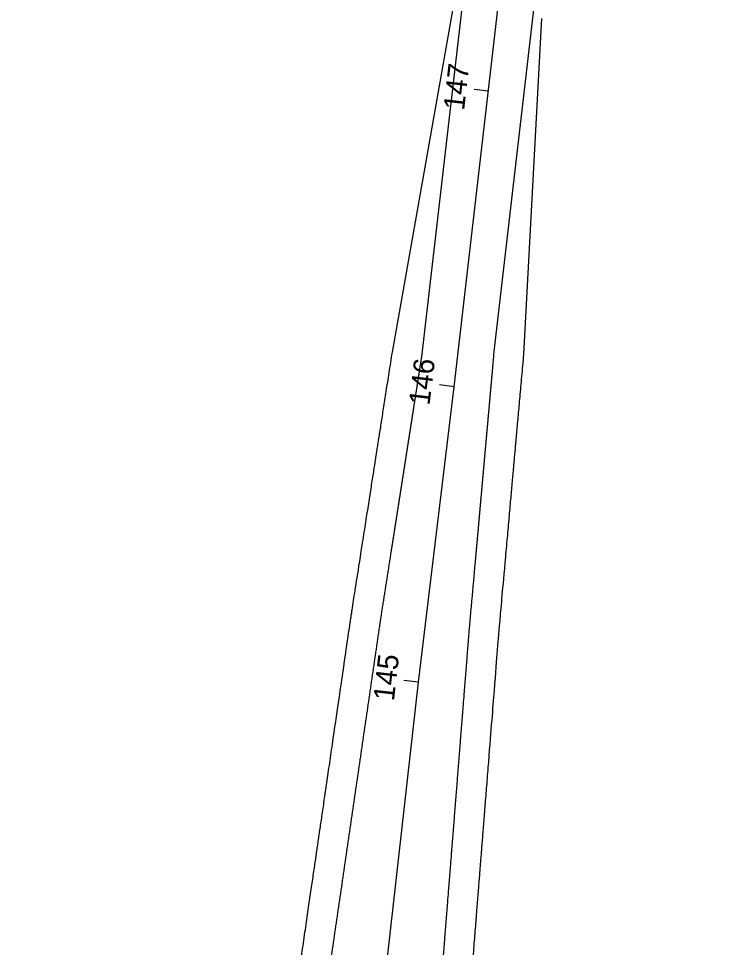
# Model space of a CAD drawing. Extents: x 2318076 to 2324211, y 613525 to 629939.
# Drawn here: x 2320544.3 to 2320778.2, y 628975.4 to 629287.5 of the extents above; entities that cross this region are included whole.
import ezdxf

# ---------------------------------------------------------------- set-up
doc = ezdxf.new("R2010")
doc.units = 0
for name, color, linetype in [('GE_P_CL_50', 7, 'Continuous'), ('PV_P_EOP', 7, 'Continuous'), ('PV_P_Shoulder', 7, 'Continuous')]:
    doc.layers.add(name, color=color, linetype=linetype)

msp = doc.modelspace()

# ---------------------------------------------------------------- linework, layer by layer
at = {"layer": 'GE_P_CL_50'}
for p, q in [((2320702.26, 629263.11), (2320697.41, 629263.67)), ((2320690.76, 629163.78), (2320685.8, 629164.39)), ((2320678.77, 629064.5), (2320673.8, 629065.06))]:
    msp.add_line(p, q, dxfattribs=at)
msp.add_lwpolyline([(2320485.22, 627375.57), (2320502.11, 627520.92), (2320519.22, 627676.47), (2320531.82, 627783.89), (2320546.8, 627927.12), (2320554.45, 627991.34), (2320572.51, 628138.41), (2320649.52, 628804.84), (2320678.77, 629064.5), (2320690.76, 629163.78), (2320713.75, 629362.45), (2320725.26, 629461.78), (2320736.97, 629561.09), (2320748.4, 629660.43), (2320759.09, 629759.86), (2320769.62, 629859.3), (2320777.51, 629931.12), (2320778.25, 629937.84)], dxfattribs=at)
at = {"layer": 'PV_P_EOP'}
for points in [[(2320679.85, 629173.88), (2320701.83, 629363.83), (2320708.13, 629418.9), (2320708.13, 629418.9)], [(2320704.21, 629175.59), (2320725.67, 629361.07), (2320731.95, 629415.91), (2320731.95, 629415.91)]]:
    msp.add_lwpolyline(points, dxfattribs=at)
for points in [[(2320669.71, 629109.04), (2320669.76, 629109.34), (2320669.81, 629109.64), (2320669.85, 629109.94), (2320669.9, 629110.24), (2320669.95, 629110.54), (2320670, 629110.84), (2320670.04, 629111.14), (2320670.09, 629111.44), (2320670.14, 629111.74), (2320670.18, 629112.04), (2320670.23, 629112.34), (2320670.28, 629112.64), (2320670.32, 629112.94), (2320670.37, 629113.24), (2320670.42, 629113.54), (2320670.47, 629113.84), (2320670.51, 629114.14), (2320670.56, 629114.44), (2320670.61, 629114.74), (2320670.65, 629115.04), (2320670.7, 629115.35), (2320670.75, 629115.65), (2320670.79, 629115.95), (2320670.84, 629116.25), (2320670.89, 629116.55), (2320670.93, 629116.85), (2320670.98, 629117.15), (2320671.03, 629117.45), (2320671.08, 629117.75), (2320671.12, 629118.05), (2320671.17, 629118.35), (2320671.22, 629118.65), (2320671.26, 629118.95), (2320671.31, 629119.25), (2320671.36, 629119.55), (2320671.4, 629119.85), (2320671.45, 629120.15), (2320671.5, 629120.45), (2320671.55, 629120.75), (2320671.59, 629121.05), (2320671.64, 629121.35), (2320671.69, 629121.65), (2320671.73, 629121.95), (2320671.78, 629122.25), (2320671.83, 629122.55), (2320671.87, 629122.85), (2320671.92, 629123.15), (2320671.97, 629123.45), (2320672.01, 629123.75), (2320672.06, 629124.05), (2320672.11, 629124.35), (2320672.16, 629124.66), (2320672.2, 629124.96), (2320672.25, 629125.26), (2320672.3, 629125.56), (2320672.34, 629125.86), (2320672.39, 629126.16), (2320672.44, 629126.46), (2320672.48, 629126.76), (2320672.53, 629127.06), (2320672.58, 629127.36), (2320672.63, 629127.66), (2320672.67, 629127.96), (2320672.72, 629128.26), (2320672.77, 629128.56), (2320672.81, 629128.86), (2320672.86, 629129.16), (2320672.91, 629129.46), (2320672.95, 629129.76), (2320673, 629130.06), (2320673.05, 629130.36), (2320673.09, 629130.66), (2320673.14, 629130.96), (2320673.19, 629131.26), (2320673.24, 629131.56), (2320673.28, 629131.86), (2320673.33, 629132.16), (2320673.38, 629132.46), (2320673.42, 629132.76), (2320673.47, 629133.06), (2320673.52, 629133.36), (2320673.56, 629133.66), (2320673.61, 629133.97), (2320673.66, 629134.27), (2320673.71, 629134.57), (2320673.75, 629134.87), (2320673.8, 629135.17), (2320673.85, 629135.47), (2320673.89, 629135.77), (2320673.94, 629136.07), (2320673.99, 629136.37), (2320674.03, 629136.67), (2320674.08, 629136.97), (2320674.13, 629137.27), (2320674.17, 629137.57), (2320674.22, 629137.87), (2320674.27, 629138.17), (2320674.32, 629138.47), (2320674.36, 629138.77), (2320674.41, 629139.07), (2320674.46, 629139.37), (2320674.5, 629139.67), (2320674.55, 629139.97), (2320674.6, 629140.27), (2320674.64, 629140.57), (2320674.69, 629140.87), (2320674.74, 629141.17), (2320674.79, 629141.47), (2320674.83, 629141.77), (2320674.88, 629142.07), (2320674.93, 629142.37), (2320674.97, 629142.67), (2320675.02, 629142.97), (2320675.07, 629143.27), (2320675.11, 629143.58), (2320675.16, 629143.88), (2320675.21, 629144.18), (2320675.25, 629144.48), (2320675.3, 629144.78), (2320675.35, 629145.08), (2320675.4, 629145.38), (2320675.44, 629145.68), (2320675.49, 629145.98), (2320675.54, 629146.28), (2320675.58, 629146.58), (2320675.63, 629146.88), (2320675.68, 629147.18), (2320675.72, 629147.48), (2320675.77, 629147.78), (2320675.82, 629148.08), (2320675.87, 629148.38), (2320675.91, 629148.68), (2320675.96, 629148.98), (2320676.01, 629149.28), (2320676.05, 629149.58), (2320676.1, 629149.88), (2320676.15, 629150.18), (2320676.19, 629150.48), (2320676.24, 629150.78), (2320676.29, 629151.08), (2320676.33, 629151.38), (2320676.38, 629151.68), (2320676.43, 629151.98), (2320676.48, 629152.28), (2320676.52, 629152.58), (2320676.57, 629152.89), (2320676.62, 629153.19), (2320676.66, 629153.49), (2320676.71, 629153.79), (2320676.76, 629154.09), (2320676.8, 629154.39), (2320676.85, 629154.69), (2320676.9, 629154.99), (2320676.95, 629155.29), (2320676.99, 629155.59), (2320677.04, 629155.89), (2320677.09, 629156.19), (2320677.13, 629156.49), (2320677.18, 629156.79), (2320677.23, 629157.09), (2320677.27, 629157.39), (2320677.32, 629157.69), (2320677.37, 629157.99), (2320677.41, 629158.29), (2320677.46, 629158.59), (2320677.51, 629158.89), (2320677.56, 629159.19), (2320677.6, 629159.49), (2320677.65, 629159.79), (2320677.7, 629160.09), (2320677.74, 629160.39), (2320677.79, 629160.69), (2320677.84, 629160.99), (2320677.88, 629161.29), (2320677.93, 629161.59), (2320677.98, 629161.89), (2320678.03, 629162.2), (2320678.07, 629162.5), (2320678.12, 629162.8), (2320678.17, 629163.1), (2320678.21, 629163.4), (2320678.26, 629163.7), (2320678.31, 629164), (2320678.35, 629164.3), (2320678.4, 629164.6), (2320678.45, 629164.9), (2320678.49, 629165.2), (2320678.54, 629165.5), (2320678.59, 629165.8), (2320678.64, 629166.1), (2320678.68, 629166.4), (2320678.73, 629166.7), (2320678.78, 629167), (2320678.82, 629167.3), (2320678.87, 629167.6), (2320678.92, 629167.9), (2320678.96, 629168.2), (2320679.01, 629168.5), (2320679.06, 629168.8), (2320679.11, 629169.1), (2320679.15, 629169.4), (2320679.2, 629169.7), (2320679.25, 629170), (2320679.29, 629170.3), (2320679.34, 629170.6), (2320679.39, 629170.9), (2320679.43, 629171.2), (2320679.48, 629171.51), (2320679.53, 629171.81), (2320679.57, 629172.11), (2320679.62, 629172.41), (2320679.67, 629172.71), (2320679.72, 629173.01), (2320679.76, 629173.3), (2320679.81, 629173.59), (2320679.85, 629173.88)], [(2320697.95, 629105.57), (2320697.97, 629105.88), (2320698, 629106.18), (2320698.03, 629106.48), (2320698.05, 629106.78), (2320698.08, 629107.09), (2320698.11, 629107.39), (2320698.14, 629107.69), (2320698.16, 629107.99), (2320698.19, 629108.3), (2320698.22, 629108.6), (2320698.24, 629108.9), (2320698.27, 629109.21), (2320698.3, 629109.51), (2320698.33, 629109.81), (2320698.35, 629110.11), (2320698.38, 629110.42), (2320698.41, 629110.72), (2320698.43, 629111.02), (2320698.46, 629111.32), (2320698.49, 629111.63), (2320698.52, 629111.93), (2320698.54, 629112.23), (2320698.57, 629112.54), (2320698.6, 629112.84), (2320698.62, 629113.14), (2320698.65, 629113.44), (2320698.68, 629113.75), (2320698.7, 629114.05), (2320698.73, 629114.35), (2320698.76, 629114.66), (2320698.79, 629114.96), (2320698.81, 629115.26), (2320698.84, 629115.56), (2320698.87, 629115.87), (2320698.89, 629116.17), (2320698.92, 629116.47), (2320698.95, 629116.77), (2320698.98, 629117.08), (2320699, 629117.38), (2320699.03, 629117.68), (2320699.06, 629117.99), (2320699.08, 629118.29), (2320699.11, 629118.59), (2320699.14, 629118.89), (2320699.17, 629119.2), (2320699.19, 629119.5), (2320699.22, 629119.8), (2320699.25, 629120.1), (2320699.27, 629120.41), (2320699.3, 629120.71), (2320699.33, 629121.01), (2320699.35, 629121.32), (2320699.38, 629121.62), (2320699.41, 629121.92), (2320699.44, 629122.22), (2320699.46, 629122.53), (2320699.49, 629122.83), (2320699.52, 629123.13), (2320699.54, 629123.44), (2320699.57, 629123.74), (2320699.6, 629124.04), (2320699.63, 629124.34), (2320699.65, 629124.65), (2320699.68, 629124.95), (2320699.71, 629125.25), (2320699.73, 629125.55), (2320699.76, 629125.86), (2320699.79, 629126.16), (2320699.82, 629126.46), (2320699.84, 629126.77), (2320699.87, 629127.07), (2320699.9, 629127.37), (2320699.92, 629127.67), (2320699.95, 629127.98), (2320699.98, 629128.28), (2320700.01, 629128.58), (2320700.03, 629128.88), (2320700.06, 629129.19), (2320700.09, 629129.49), (2320700.11, 629129.79), (2320700.14, 629130.1), (2320700.17, 629130.4), (2320700.19, 629130.7), (2320700.22, 629131), (2320700.25, 629131.31), (2320700.28, 629131.61), (2320700.3, 629131.91), (2320700.33, 629132.22), (2320700.36, 629132.52), (2320700.38, 629132.82), (2320700.41, 629133.12), (2320700.44, 629133.43), (2320700.47, 629133.73), (2320700.49, 629134.03), (2320700.52, 629134.33), (2320700.55, 629134.64), (2320700.57, 629134.94), (2320700.6, 629135.24), (2320700.63, 629135.55), (2320700.66, 629135.85), (2320700.68, 629136.15), (2320700.71, 629136.45), (2320700.74, 629136.76), (2320700.76, 629137.06), (2320700.79, 629137.36), (2320700.82, 629137.66), (2320700.84, 629137.97), (2320700.87, 629138.27), (2320700.9, 629138.57), (2320700.93, 629138.88), (2320700.95, 629139.18), (2320700.98, 629139.48), (2320701.01, 629139.78), (2320701.03, 629140.09), (2320701.06, 629140.39), (2320701.09, 629140.69), (2320701.12, 629141), (2320701.14, 629141.3), (2320701.17, 629141.6), (2320701.2, 629141.9), (2320701.22, 629142.21), (2320701.25, 629142.51), (2320701.28, 629142.81), (2320701.31, 629143.11), (2320701.33, 629143.42), (2320701.36, 629143.72), (2320701.39, 629144.02), (2320701.41, 629144.33), (2320701.44, 629144.63), (2320701.47, 629144.93), (2320701.49, 629145.23), (2320701.52, 629145.54), (2320701.55, 629145.84), (2320701.58, 629146.14), (2320701.6, 629146.44), (2320701.63, 629146.75), (2320701.66, 629147.05), (2320701.68, 629147.35), (2320701.71, 629147.66), (2320701.74, 629147.96), (2320701.77, 629148.26), (2320701.79, 629148.56), (2320701.82, 629148.87), (2320701.85, 629149.17), (2320701.87, 629149.47), (2320701.9, 629149.78), (2320701.93, 629150.08), (2320701.96, 629150.38), (2320701.98, 629150.68), (2320702.01, 629150.99), (2320702.04, 629151.29), (2320702.06, 629151.59), (2320702.09, 629151.89), (2320702.12, 629152.2), (2320702.14, 629152.5), (2320702.17, 629152.8), (2320702.2, 629153.11), (2320702.23, 629153.41), (2320702.25, 629153.71), (2320702.28, 629154.01), (2320702.31, 629154.32), (2320702.33, 629154.62), (2320702.36, 629154.92), (2320702.39, 629155.22), (2320702.42, 629155.53), (2320702.44, 629155.83), (2320702.47, 629156.13), (2320702.5, 629156.44), (2320702.52, 629156.74), (2320702.55, 629157.04), (2320702.58, 629157.34), (2320702.61, 629157.65), (2320702.63, 629157.95), (2320702.66, 629158.25), (2320702.69, 629158.56), (2320702.71, 629158.86), (2320702.74, 629159.16), (2320702.77, 629159.46), (2320702.79, 629159.77), (2320702.82, 629160.07), (2320702.85, 629160.37), (2320702.88, 629160.67), (2320702.9, 629160.98), (2320702.93, 629161.28), (2320702.96, 629161.58), (2320702.98, 629161.89), (2320703.01, 629162.19), (2320703.04, 629162.49), (2320703.07, 629162.79), (2320703.09, 629163.1), (2320703.12, 629163.4), (2320703.15, 629163.7), (2320703.17, 629164), (2320703.2, 629164.31), (2320703.23, 629164.61), (2320703.26, 629164.91), (2320703.28, 629165.22), (2320703.31, 629165.52), (2320703.34, 629165.82), (2320703.36, 629166.12), (2320703.39, 629166.43), (2320703.42, 629166.73), (2320703.44, 629167.03), (2320703.47, 629167.34), (2320703.5, 629167.64), (2320703.53, 629167.94), (2320703.55, 629168.24), (2320703.58, 629168.55), (2320703.61, 629168.85), (2320703.63, 629169.15), (2320703.66, 629169.45), (2320703.69, 629169.76), (2320703.72, 629170.06), (2320703.74, 629170.36), (2320703.77, 629170.67), (2320703.8, 629170.97), (2320703.93, 629172.51), (2320704.07, 629174.05), (2320704.21, 629175.59)]]:
    msp.add_open_spline(points, degree=3, dxfattribs=at)
for points in [[(2320659.7, 629042.15), (2320659.83, 629043.06), (2320659.97, 629043.96), (2320660.1, 629044.86), (2320660.23, 629045.76), (2320660.36, 629046.67), (2320660.49, 629047.57), (2320660.63, 629048.47), (2320660.76, 629049.37), (2320660.89, 629050.27), (2320661.02, 629051.18), (2320661.15, 629052.08), (2320661.29, 629052.98), (2320661.42, 629053.88), (2320661.55, 629054.79), (2320661.68, 629055.69), (2320661.81, 629056.59), (2320661.94, 629057.49), (2320662.08, 629058.4), (2320662.21, 629059.3), (2320662.34, 629060.2), (2320662.47, 629061.1), (2320662.6, 629062), (2320662.74, 629062.91), (2320662.87, 629063.81), (2320663, 629064.71), (2320663.13, 629065.61), (2320663.26, 629066.52), (2320663.4, 629067.42), (2320663.53, 629068.32), (2320663.66, 629069.22), (2320663.79, 629070.13), (2320663.92, 629071.03), (2320664.05, 629071.93), (2320664.19, 629072.83), (2320664.32, 629073.73), (2320664.45, 629074.64), (2320664.58, 629075.54), (2320664.71, 629076.44), (2320664.85, 629077.34), (2320664.98, 629078.25), (2320665.11, 629079.15), (2320665.24, 629080.05), (2320665.37, 629080.95), (2320665.5, 629081.86), (2320665.64, 629082.76), (2320665.77, 629083.66), (2320665.9, 629084.56), (2320666.05, 629085.61), (2320666.19, 629086.51), (2320666.33, 629087.42), (2320666.47, 629088.32), (2320666.62, 629089.22), (2320666.76, 629090.12), (2320666.9, 629091.02), (2320667.04, 629091.92), (2320667.18, 629092.82), (2320667.32, 629093.72), (2320667.46, 629094.62), (2320667.6, 629095.52), (2320667.74, 629096.43), (2320667.88, 629097.33), (2320668.02, 629098.23), (2320668.16, 629099.13), (2320668.31, 629100.03), (2320668.45, 629100.93), (2320668.59, 629101.83), (2320668.73, 629102.73), (2320668.87, 629103.63), (2320669.01, 629104.53), (2320669.15, 629105.43), (2320669.29, 629106.34), (2320669.43, 629107.24), (2320669.57, 629108.14), (2320669.71, 629109.04)], [(2320692.39, 629038.47), (2320692.46, 629039.38), (2320692.53, 629040.29), (2320692.6, 629041.2), (2320692.67, 629042.11), (2320692.75, 629043.02), (2320692.82, 629043.93), (2320692.89, 629044.84), (2320692.96, 629045.74), (2320693.03, 629046.65), (2320693.11, 629047.56), (2320693.18, 629048.47), (2320693.25, 629049.38), (2320693.32, 629050.29), (2320693.4, 629051.2), (2320693.47, 629052.11), (2320693.54, 629053.02), (2320693.61, 629053.93), (2320693.68, 629054.83), (2320693.76, 629055.74), (2320693.83, 629056.65), (2320693.9, 629057.56), (2320693.97, 629058.47), (2320694.05, 629059.38), (2320694.12, 629060.29), (2320694.19, 629061.2), (2320694.26, 629062.11), (2320694.33, 629063.02), (2320694.41, 629063.93), (2320694.48, 629064.83), (2320694.55, 629065.74), (2320694.62, 629066.65), (2320694.69, 629067.56), (2320694.77, 629068.47), (2320694.84, 629069.38), (2320694.91, 629070.29), (2320694.98, 629071.2), (2320695.06, 629072.11), (2320695.13, 629073.02), (2320695.2, 629073.92), (2320695.27, 629074.83), (2320695.34, 629075.74), (2320695.42, 629076.65), (2320695.49, 629077.56), (2320695.56, 629078.47), (2320695.63, 629079.38), (2320695.71, 629080.29), (2320695.78, 629081.2), (2320695.83, 629081.96), (2320695.92, 629082.87), (2320696, 629083.77), (2320696.08, 629084.68), (2320696.16, 629085.59), (2320696.24, 629086.5), (2320696.32, 629087.41), (2320696.4, 629088.32), (2320696.48, 629089.22), (2320696.57, 629090.13), (2320696.65, 629091.04), (2320696.73, 629091.95), (2320696.81, 629092.86), (2320696.89, 629093.76), (2320696.97, 629094.67), (2320697.05, 629095.58), (2320697.13, 629096.49), (2320697.22, 629097.4), (2320697.3, 629098.31), (2320697.38, 629099.21), (2320697.46, 629100.12), (2320697.54, 629101.03), (2320697.62, 629101.94), (2320697.7, 629102.85), (2320697.78, 629103.76), (2320697.87, 629104.66), (2320697.95, 629105.57)], [(2320649.95, 628975.38), (2320650.08, 628976.28), (2320650.21, 628977.19), (2320650.34, 628978.09), (2320650.47, 628978.99), (2320650.6, 628979.89), (2320650.74, 628980.8), (2320650.87, 628981.7), (2320651, 628982.6), (2320651.13, 628983.5), (2320651.26, 628984.4), (2320651.4, 628985.31), (2320651.53, 628986.21), (2320651.66, 628987.11), (2320651.79, 628988.01), (2320651.92, 628988.92), (2320652.06, 628989.82), (2320652.19, 628990.72), (2320652.32, 628991.62), (2320652.45, 628992.53), (2320652.58, 628993.43), (2320652.71, 628994.33), (2320652.85, 628995.23), (2320652.98, 628996.13), (2320653.11, 628997.04), (2320653.24, 628997.94), (2320653.37, 628998.84), (2320653.51, 628999.74), (2320653.64, 629000.65), (2320653.77, 629001.55), (2320653.9, 629002.45), (2320654.03, 629003.35), (2320654.16, 629004.26), (2320654.3, 629005.16), (2320654.43, 629006.06), (2320654.56, 629006.96), (2320654.69, 629007.87), (2320654.82, 629008.77), (2320654.96, 629009.67), (2320655.09, 629010.57), (2320655.22, 629011.47), (2320655.35, 629012.38), (2320655.48, 629013.28), (2320655.62, 629014.18), (2320655.75, 629015.08), (2320655.88, 629015.99), (2320656.01, 629016.89), (2320656.14, 629017.79), (2320656.27, 629018.69), (2320656.41, 629019.6), (2320656.54, 629020.5), (2320656.67, 629021.4), (2320656.8, 629022.3), (2320656.93, 629023.2), (2320657.07, 629024.11), (2320657.2, 629025.01), (2320657.33, 629025.91), (2320657.46, 629026.81), (2320657.59, 629027.72), (2320657.73, 629028.62), (2320657.86, 629029.52), (2320657.99, 629030.42), (2320658.12, 629031.33), (2320658.25, 629032.23), (2320658.38, 629033.13), (2320658.52, 629034.03), (2320658.65, 629034.93), (2320658.78, 629035.84), (2320658.91, 629036.74), (2320659.04, 629037.64), (2320659.18, 629038.54), (2320659.31, 629039.45), (2320659.44, 629040.35), (2320659.57, 629041.25), (2320659.7, 629042.15)], [(2320687.04, 628971.2), (2320687.12, 628972.11), (2320687.19, 628973.02), (2320687.26, 628973.93), (2320687.33, 628974.84), (2320687.4, 628975.75), (2320687.48, 628976.66), (2320687.55, 628977.57), (2320687.62, 628978.48), (2320687.69, 628979.38), (2320687.77, 628980.29), (2320687.84, 628981.2), (2320687.91, 628982.11), (2320687.98, 628983.02), (2320688.05, 628983.93), (2320688.13, 628984.84), (2320688.2, 628985.75), (2320688.27, 628986.66), (2320688.34, 628987.57), (2320688.42, 628988.47), (2320688.49, 628989.38), (2320688.56, 628990.29), (2320688.63, 628991.2), (2320688.7, 628992.11), (2320688.78, 628993.02), (2320688.85, 628993.93), (2320688.92, 628994.84), (2320688.99, 628995.75), (2320689.07, 628996.66), (2320689.14, 628997.57), (2320689.21, 628998.47), (2320689.28, 628999.38), (2320689.35, 629000.29), (2320689.43, 629001.2), (2320689.5, 629002.11), (2320689.57, 629003.02), (2320689.64, 629003.93), (2320689.71, 629004.84), (2320689.79, 629005.75), (2320689.86, 629006.66), (2320689.93, 629007.56), (2320690, 629008.47), (2320690.08, 629009.38), (2320690.15, 629010.29), (2320690.22, 629011.2), (2320690.29, 629012.11), (2320690.36, 629013.02), (2320690.44, 629013.93), (2320690.51, 629014.84), (2320690.58, 629015.75), (2320690.65, 629016.65), (2320690.73, 629017.56), (2320690.8, 629018.47), (2320690.87, 629019.38), (2320690.94, 629020.29), (2320691.01, 629021.2), (2320691.09, 629022.11), (2320691.16, 629023.02), (2320691.23, 629023.93), (2320691.3, 629024.84), (2320691.37, 629025.75), (2320691.45, 629026.65), (2320691.52, 629027.56), (2320691.59, 629028.47), (2320691.66, 629029.38), (2320691.74, 629030.29), (2320691.81, 629031.2), (2320691.88, 629032.11), (2320691.95, 629033.02), (2320692.02, 629033.93), (2320692.1, 629034.84), (2320692.17, 629035.74), (2320692.24, 629036.65), (2320692.31, 629037.56), (2320692.39, 629038.47)], [(2320640.19, 628908.61), (2320640.32, 628909.51), (2320640.45, 628910.41), (2320640.58, 628911.32), (2320640.72, 628912.22), (2320640.85, 628913.12), (2320640.98, 628914.02), (2320641.11, 628914.93), (2320641.24, 628915.83), (2320641.37, 628916.73), (2320641.51, 628917.63), (2320641.64, 628918.54), (2320641.77, 628919.44), (2320641.9, 628920.34), (2320642.03, 628921.24), (2320642.17, 628922.14), (2320642.3, 628923.05), (2320642.43, 628923.95), (2320642.56, 628924.85), (2320642.69, 628925.75), (2320642.82, 628926.66), (2320642.96, 628927.56), (2320643.09, 628928.46), (2320643.22, 628929.36), (2320643.35, 628930.27), (2320643.48, 628931.17), (2320643.62, 628932.07), (2320643.75, 628932.97), (2320643.88, 628933.87), (2320644.01, 628934.78), (2320644.14, 628935.68), (2320644.28, 628936.58), (2320644.41, 628937.48), (2320644.54, 628938.39), (2320644.67, 628939.29), (2320644.8, 628940.19), (2320644.93, 628941.09), (2320645.07, 628942), (2320645.2, 628942.9), (2320645.33, 628943.8), (2320645.46, 628944.7), (2320645.59, 628945.6), (2320645.73, 628946.51), (2320645.86, 628947.41), (2320645.99, 628948.31), (2320646.12, 628949.21), (2320646.25, 628950.12), (2320646.39, 628951.02), (2320646.52, 628951.92), (2320646.65, 628952.82), (2320646.78, 628953.73), (2320646.91, 628954.63), (2320647.04, 628955.53), (2320647.18, 628956.43), (2320647.31, 628957.34), (2320647.44, 628958.24), (2320647.57, 628959.14), (2320647.7, 628960.04), (2320647.84, 628960.94), (2320647.97, 628961.85), (2320648.1, 628962.75), (2320648.23, 628963.65), (2320648.36, 628964.55), (2320648.49, 628965.46), (2320648.63, 628966.36), (2320648.76, 628967.26), (2320648.89, 628968.16), (2320649.02, 628969.07), (2320649.15, 628969.97), (2320649.29, 628970.87), (2320649.42, 628971.77), (2320649.55, 628972.67), (2320649.68, 628973.58), (2320649.81, 628974.48), (2320649.95, 628975.38)]]:
    msp.add_spline(points, degree=3, dxfattribs=at)
at = {"layer": 'PV_P_Shoulder'}
for p, q in [((2320669.97, 629175.43), (2320690.38, 629290.93)), ((2320714.17, 629174.7), (2320720.18, 629287.5))]:
    msp.add_line(p, q, dxfattribs=at)
for points, degree in [([(2320659.83, 629110.58), (2320663.21, 629132.2), (2320666.59, 629153.81), (2320669.97, 629175.43)], 2), ([(2320707.91, 629104.68), (2320709.99, 629128.02), (2320712.08, 629151.36), (2320714.17, 629174.7)], 2), ([(2320649.81, 629043.6), (2320651.44, 629054.75), (2320653.48, 629068.69), (2320655.54, 629082.81), (2320655.97, 629085.78), (2320656, 629085.97), (2320656, 629085.99), (2320656, 629086), (2320656.01, 629086.01), (2320656.01, 629086.03), (2320656.01, 629086.07), (2320656.02, 629086.13), (2320656.04, 629086.24), (2320656.05, 629086.32), (2320656.09, 629086.59), (2320656.12, 629086.81), (2320656.16, 629087.09), (2320656.17, 629087.12), (2320656.17, 629087.16), (2320656.17, 629087.16), (2320656.17, 629087.17), (2320656.17, 629087.18), (2320656.18, 629087.2), (2320656.19, 629087.26), (2320656.21, 629087.4), (2320656.34, 629088.22), (2320656.68, 629090.4), (2320657.88, 629098.05), (2320658.96, 629105.01), (2320659.83, 629110.58)], 3), ([(2320702.35, 629037.68), (2320703.24, 629048.87), (2320704.35, 629062.85), (2320705.48, 629077.01), (2320705.72, 629080.02), (2320705.73, 629080.26), (2320705.74, 629080.34), (2320705.74, 629080.38), (2320705.75, 629080.4), (2320705.75, 629080.4), (2320705.75, 629080.41), (2320705.75, 629080.42), (2320705.76, 629080.56), (2320705.77, 629080.69), (2320705.78, 629080.88), (2320705.79, 629080.95), (2320705.79, 629081.02), (2320705.79, 629081.04), (2320705.79, 629081.06), (2320705.79, 629081.06), (2320705.79, 629081.06), (2320705.79, 629081.07), (2320705.79, 629081.07), (2320705.79, 629081.07), (2320705.79, 629081.07), (2320705.8, 629081.08), (2320705.81, 629081.27), (2320705.89, 629082.15), (2320706.09, 629084.42), (2320706.78, 629092.11), (2320707.41, 629099.09), (2320707.91, 629104.68)], 3), ([(2320640.05, 628976.83), (2320643.3, 628999.08), (2320646.56, 629021.34), (2320649.81, 629043.6)], 2), ([(2320697.01, 628970.41), (2320698.79, 628992.83), (2320700.57, 629015.26), (2320702.35, 629037.68)], 2), ([(2320630.29, 628910.06), (2320633.55, 628932.31), (2320636.8, 628954.57), (2320640.05, 628976.83)], 2)]:
    msp.add_open_spline(points, degree=degree, dxfattribs=at)

# ---------------------------------------------------------------- texts
at = {"layer": 'GE_P_CL_50'}
for s, rotation, p in [('147', 83.4799, (2320694.07, 629256.45)), ('146', 83.0008, (2320682.42, 629157.33)), ('145', 83.5732, (2320670.49, 629058))]:
    msp.add_text(s, height=7, rotation=rotation, dxfattribs=at).set_placement(p)

doc.saveas('drawing.dxf')
